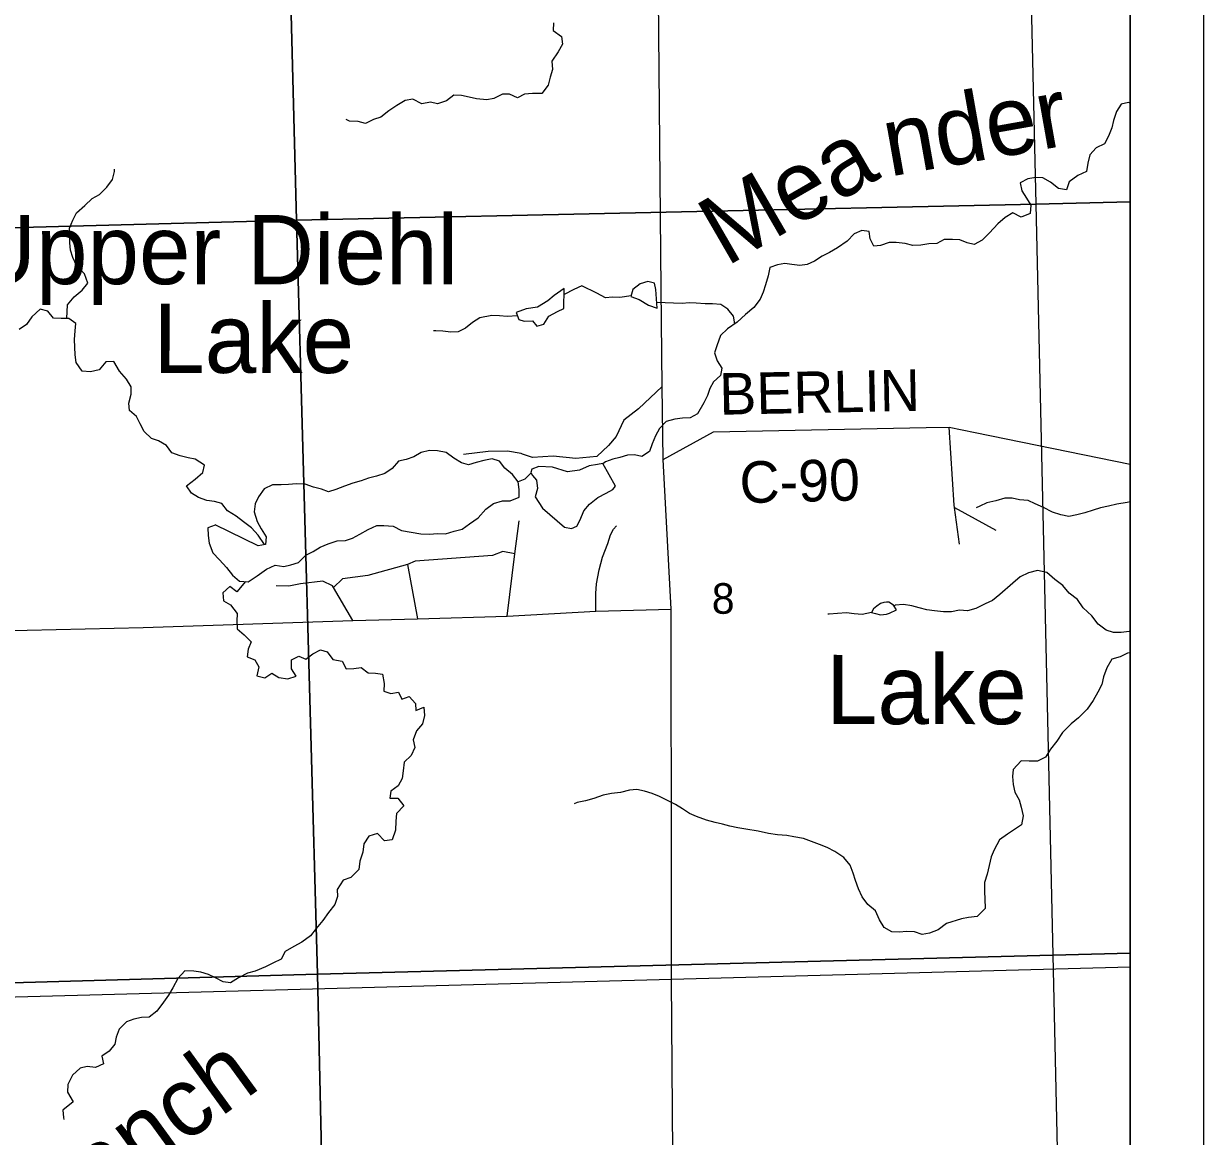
# Model space of a CAD drawing. Extents: x 0 to 34, y 0 to 22.
# Drawn here: x 8.73 to 10.344, y 14.503 to 16.025 of the extents above; entities that cross this region are included whole.
import ezdxf

# ---------------------------------------------------------------- set-up
doc = ezdxf.new("R2010")
doc.units = 0
for name, color, linetype in [('GM_X_Corporation', 7, 'Continuous'), ('GM_X_County_Road', 7, 'Continuous'), ('GM_X_County_Road_Text', 7, 'Continuous'), ('GM_X_Minor_Lake', 7, 'Continuous'), ('GM_X_Minor_Lake_Text', 7, 'Continuous'), ('GM_X_Minor_River', 7, 'Continuous'), ('GM_X_Minor_River_Text', 7, 'Continuous'), ('GM_X_Section_Text', 7, 'Continuous'), ('GM_X_State_Route', 7, 'Continuous'), ('GM_X_Township_Road', 7, 'Continuous'), ('SH_Data', 7, 'Continuous')]:
    doc.layers.add(name, color=color, linetype=linetype)

msp = doc.modelspace()

# ---------------------------------------------------------------- linework, layer by layer
at = {"layer": 'GM_X_Corporation'}
msp.add_lwpolyline([(7.068, 16.109), (7.0714, 16.0063), (7.0745, 15.896), (7.0787, 15.766), (7.0827, 15.6404), (7.0859, 15.5239), (7.0914, 15.3396), (7.0961, 15.1801), (7.0965, 15.1593), (7.1012, 14.6522), (7.1045, 14.5502), (7.1291, 13.6578), (8.1719, 13.6806), (8.628, 13.6922), (9.6344, 13.7177), (9.7208, 13.7198), (10.2438, 13.7323), (10.2438, 18.8341)], dxfattribs=at)
for points in [[(10.0909, 16.801), (10.1146, 15.7786), (9.1033, 15.7563), (9.0769, 16.778)], [(10.2438, 15.7815), (10.2438, 16.8039), (10.0909, 16.801), (10.1146, 15.7786)], [(9.0769, 16.778), (9.1033, 15.7563), (8.0922, 15.7295), (8.0702, 16.7576)], [(10.1146, 15.7786), (10.1377, 14.7507), (9.132, 14.7248), (9.1033, 15.7563)], [(10.2438, 14.7535), (10.2438, 15.7815), (10.1146, 15.7786), (10.1377, 14.7507)], [(9.1033, 15.7563), (9.132, 14.7248), (8.1182, 14.6962), (8.0922, 15.7295)], [(10.2438, 13.7318), (10.2438, 14.7535), (10.1377, 14.7507), (10.1605, 13.7298)], [(9.132, 14.7248), (10.1377, 14.7507), (10.1605, 13.7298), (9.7319, 13.7196), (9.155, 13.7064)], [(8.1182, 14.6962), (9.132, 14.7248), (9.155, 13.7064), (8.7319, 13.6926), (8.142, 13.6801)]]:
    msp.add_lwpolyline(points, close=True, dxfattribs=at)
at = {"layer": 'GM_X_County_Road'}
for p, q in [((9.6156, 15.2242), (9.6049, 15.4288)), ((10.2438, 14.7344), (9.6162, 14.7175))]:
    msp.add_line(p, q, dxfattribs=at)
for points in [[(9.6049, 15.4288), (9.6738, 15.4668), (9.9647, 15.4727), (9.9959, 15.4734), (10.0314, 15.4658), (10.2438, 15.4225)], [(7.0967, 15.1587), (8.735, 15.1956), (8.8937, 15.199), (9.1804, 15.2086), (9.2686, 15.2111), (9.3914, 15.2147), (9.5125, 15.2213), (9.6156, 15.2242)], [(9.6162, 14.7175), (8.5998, 14.6899), (7.1014, 14.6516)]]:
    msp.add_lwpolyline(points, dxfattribs=at)
at = {"layer": 'GM_X_Minor_Lake'}
for points in [[(9.5948, 15.6615), (9.5928, 15.6702), (9.5837, 15.6727), (9.5735, 15.6696), (9.5633, 15.6615), (9.5608, 15.6519), (9.5718, 15.6479), (9.5848, 15.6401), (9.5967, 15.636)], [(9.4692, 15.663), (9.4556, 15.6533), (9.447, 15.646), (9.4331, 15.6375), (9.4175, 15.635), (9.4039, 15.6303), (9.4075, 15.6204), (9.4147, 15.6182), (9.4261, 15.6188), (9.4319, 15.6116), (9.4417, 15.6144), (9.4484, 15.6251), (9.4605, 15.6313), (9.4691, 15.6356)], [(9.4691, 15.6356), (9.4692, 15.663)], [(9.5967, 15.636), (9.5948, 15.6615)], [(8.9919, 15.3396), (8.9919, 15.3392), (8.9821, 15.3357), (8.9826, 15.3251), (8.9839, 15.3145), (8.989, 15.3012), (8.9978, 15.2915), (9.0075, 15.281), (9.0155, 15.2709), (9.0251, 15.2626), (9.0373, 15.2617), (9.0496, 15.2698), (9.062, 15.2791), (9.074, 15.2845), (9.0858, 15.2828), (9.0956, 15.2848), (9.1058, 15.288), (9.1159, 15.298), (9.126, 15.3031), (9.1358, 15.3089), (9.1467, 15.3136), (9.1591, 15.3179), (9.1701, 15.3181), (9.1799, 15.3213), (9.19, 15.3267), (9.2013, 15.3333), (9.213, 15.3388), (9.2228, 15.3385), (9.2353, 15.3379), (9.2468, 15.332), (9.26, 15.3295), (9.2733, 15.3274), (9.2858, 15.3269), (9.2957, 15.3277), (9.307, 15.3275), (9.3187, 15.3311), (9.33, 15.3335), (9.3401, 15.3409), (9.3518, 15.349), (9.3622, 15.3609), (9.3727, 15.3686), (9.3851, 15.3726), (9.3954, 15.3723), (9.4078, 15.3774), (9.408, 15.3881), (9.4063, 15.3983), (9.3986, 15.4084), (9.3883, 15.417), (9.381, 15.4268), (9.3711, 15.4297), (9.3597, 15.4277), (9.3488, 15.4249), (9.3386, 15.4217), (9.3291, 15.4246), (9.3184, 15.4309), (9.3081, 15.4387), (9.2963, 15.4409), (9.2853, 15.4415), (9.274, 15.4387), (9.2639, 15.4328), (9.2533, 15.4289), (9.2428, 15.4269), (9.2342, 15.4165), (9.2241, 15.4099), (9.2128, 15.4063), (9.2018, 15.4035), (9.1917, 15.4), (9.1804, 15.3964), (9.1691, 15.3925), (9.157, 15.3881), (9.1472, 15.3846), (9.1373, 15.3886), (9.1263, 15.3911), (9.1153, 15.3952), (9.1031, 15.3958), (9.0925, 15.3949), (9.0823, 15.3943), (9.0706, 15.3942), (9.0589, 15.3887), (9.0515, 15.378), (9.0467, 15.3684), (9.0454, 15.3574), (9.0493, 15.3442), (9.0548, 15.334), (9.0618, 15.3231), (9.0608, 15.3128), (9.0509, 15.3108)], [(9.5222, 15.4234), (9.515, 15.4222), (9.5037, 15.4205), (9.4905, 15.4146), (9.4739, 15.4121), (9.4534, 15.4187), (9.4348, 15.4196), (9.425, 15.4156), (9.424, 15.4114), (9.4259, 15.4073), (9.4317, 15.4005), (9.433, 15.3892), (9.4297, 15.3781), (9.4398, 15.3623), (9.4697, 15.3365), (9.4795, 15.3344), (9.4867, 15.3379), (9.4915, 15.3463), (9.4962, 15.3589), (9.5041, 15.3677), (9.5153, 15.377), (9.5269, 15.3828), (9.536, 15.3879), (9.5397, 15.3925)], [(9.5397, 15.3925), (9.5222, 15.4234)], [(9.0509, 15.3108), (8.9919, 15.3396)], [(9.9198, 15.2298), (9.9137, 15.2339), (9.9103, 15.2339), (9.9065, 15.2334), (9.9023, 15.2319), (9.8971, 15.2284), (9.8926, 15.2245), (9.8896, 15.2195), (9.8953, 15.2181), (9.9022, 15.2163), (9.9101, 15.2172), (9.9146, 15.2187), (9.924, 15.2234)], [(9.924, 15.2234), (9.9198, 15.2298)]]:
    msp.add_lwpolyline(points, dxfattribs=at)
at = {"layer": 'GM_X_Minor_River'}
for points in [[(9.4547, 16.0264), (9.4544, 16.0161), (9.4656, 16.0079), (9.4672, 15.9973), (9.4613, 15.987), (9.4523, 15.974), (9.4536, 15.9626), (9.4503, 15.9523), (9.4474, 15.9412), (9.4388, 15.9297), (9.4263, 15.9299), (9.4153, 15.929), (9.4055, 15.924), (9.3948, 15.9288), (9.385, 15.9287), (9.3733, 15.9232), (9.3634, 15.9212), (9.3497, 15.9225), (9.3395, 15.9247), (9.3288, 15.9272), (9.3185, 15.9275), (9.3084, 15.9198), (9.2963, 15.9158), (9.2864, 15.918), (9.2747, 15.9156), (9.2624, 15.9219), (9.2518, 15.9202), (9.2405, 15.9136), (9.2296, 15.9059), (9.2187, 15.8974), (9.2085, 15.8942), (9.1976, 15.8888), (9.1877, 15.8913), (9.1759, 15.8919), (9.1713, 15.8942)], [(10.2438, 15.9167), (10.2414, 15.9174), (10.2315, 15.915), (10.2248, 15.9051), (10.2208, 15.8929), (10.2187, 15.883), (10.2139, 15.8715), (10.2083, 15.8608), (10.197, 15.8557), (10.1884, 15.8458), (10.1859, 15.8347), (10.1837, 15.8229), (10.172, 15.8178), (10.1604, 15.8089), (10.1564, 15.7979), (10.1457, 15.8), (10.1346, 15.8086), (10.1243, 15.8146), (10.1144, 15.8148), (10.1038, 15.8132), (10.0932, 15.8077), (10.0953, 15.7967), (10.1018, 15.7866), (10.1077, 15.7768), (10.107, 15.7657), (10.0946, 15.7606), (10.0831, 15.7666), (10.0726, 15.76), (10.0624, 15.7515), (10.0512, 15.7392), (10.0411, 15.7292), (10.0302, 15.7234), (10.0206, 15.7255), (10.0107, 15.7296), (10.0008, 15.7302), (9.9891, 15.7301)], [(8.7891, 15.622), (8.79, 15.6406), (8.7993, 15.6517), (8.8102, 15.6606), (8.8176, 15.6705), (8.8133, 15.683), (8.8025, 15.6943), (8.7974, 15.7052), (8.7939, 15.7154), (8.7934, 15.7256), (8.7932, 15.7355), (8.7927, 15.7454), (8.7971, 15.7564), (8.8023, 15.7664), (8.8135, 15.7764), (8.8236, 15.786), (8.8337, 15.7915), (8.8438, 15.8015), (8.8516, 15.8122), (8.8545, 15.8229), (8.8544, 15.8263)], [(9.9891, 15.7301), (9.9793, 15.7247), (9.9683, 15.7241), (9.9573, 15.7225), (9.9463, 15.722), (9.936, 15.7245), (9.9235, 15.7259), (9.914, 15.7258), (9.9023, 15.7218), (9.8928, 15.7209), (9.8881, 15.7311), (9.8868, 15.741), (9.8766, 15.7424), (9.866, 15.7377), (9.8563, 15.7277), (9.8431, 15.7188), (9.8325, 15.7122), (9.8224, 15.7072), (9.8118, 15.7002), (9.802, 15.6959), (9.7918, 15.6946), (9.7807, 15.696), (9.7712, 15.6974), (9.7614, 15.6954), (9.7508, 15.6915), (9.7483, 15.6801), (9.745, 15.6679), (9.7418, 15.6579), (9.7373, 15.6484), (9.7287, 15.6369), (9.7175, 15.6272), (9.7062, 15.6169), (9.693, 15.608), (9.6833, 15.5987), (9.6782, 15.5846), (9.6752, 15.5751), (9.6788, 15.5641), (9.685, 15.5539), (9.6832, 15.544), (9.6735, 15.5355), (9.6687, 15.526), (9.6654, 15.5164), (9.6606, 15.5065), (9.6516, 15.4916), (9.6418, 15.4861), (9.6312, 15.4856), (9.621, 15.4844), (9.6089, 15.4808), (9.5999, 15.4712), (9.5943, 15.4612), (9.5899, 15.4505), (9.5859, 15.4399), (9.5757, 15.4329), (9.5654, 15.4354), (9.5559, 15.4349), (9.5457, 15.4318), (9.5359, 15.4294), (9.5261, 15.4258), (9.5223, 15.4233)], [(9.5611, 15.653), (9.5456, 15.6506), (9.5357, 15.6512), (9.5259, 15.65), (9.514, 15.6567), (9.4934, 15.6667), (9.4828, 15.6616), (9.4692, 15.655)], [(9.703, 15.6147), (9.7012, 15.6251), (9.6935, 15.6349), (9.6839, 15.6413), (9.6721, 15.6419), (9.6622, 15.6422), (9.6501, 15.6428), (9.6402, 15.6434), (9.6307, 15.6425), (9.619, 15.6428), (9.6076, 15.6434), (9.5961, 15.6437)], [(9.0597, 15.3126), (9.0507, 15.3256), (9.0415, 15.3353), (9.0308, 15.3436), (9.0209, 15.3514), (9.009, 15.3588), (9.0009, 15.3686), (8.991, 15.3715), (8.9804, 15.3729), (8.9694, 15.3769), (8.9598, 15.3828), (8.9529, 15.393), (8.9645, 15.4019), (8.975, 15.4111), (8.9775, 15.4214), (8.9645, 15.4296), (8.955, 15.4314), (8.944, 15.4339), (8.9329, 15.4383), (8.9256, 15.448), (8.9145, 15.4547), (8.9047, 15.4576), (8.8951, 15.4674), (8.8896, 15.4779), (8.8842, 15.4877), (8.8746, 15.4959), (8.8741, 15.5062), (8.8769, 15.5184), (8.8772, 15.5286), (8.8706, 15.5388), (8.861, 15.5497), (8.8532, 15.5632), (8.8426, 15.5627), (8.8333, 15.5519), (8.8216, 15.5488), (8.8102, 15.5501), (8.8017, 15.5618), (8.8005, 15.572), (8.7994, 15.5932), (8.8004, 15.605), (8.8014, 15.6149), (8.7918, 15.622), (8.7812, 15.6218), (8.771, 15.6225), (8.7633, 15.6322), (8.7526, 15.6348), (8.741, 15.6243), (8.734, 15.6136), (8.7239, 15.6067)], [(9.4055, 15.6258), (9.3915, 15.6248), (9.3808, 15.6258), (9.3706, 15.6261), (9.3539, 15.6228), (9.3441, 15.6166), (9.3344, 15.6089), (9.3242, 15.6035), (9.3143, 15.6033), (9.3033, 15.6047), (9.2938, 15.605), (9.2908, 15.605)], [(9.4243, 15.4108), (9.4155, 15.4021), (9.4063, 15.3983)], [(10.2438, 15.371), (10.2396, 15.37), (10.2256, 15.3679), (10.2139, 15.3651), (10.203, 15.3627), (10.1932, 15.3595), (10.1815, 15.3559), (10.1709, 15.3535), (10.1596, 15.3511), (10.1486, 15.3532), (10.1372, 15.3568), (10.125, 15.3631), (10.1139, 15.3683), (10.104, 15.3731), (10.0923, 15.3737), (10.082, 15.3762), (10.0722, 15.3761), (10.0601, 15.3725), (10.0477, 15.3697), (10.0379, 15.365), (10.033, 15.363)], [(10.2438, 15.1938), (10.2421, 15.1935), (10.2311, 15.1922), (10.2209, 15.1921), (10.211, 15.1954), (10.1999, 15.2036), (10.1911, 15.2152), (10.1795, 15.2261), (10.1718, 15.2374), (10.16, 15.2463), (10.1515, 15.2568), (10.1404, 15.265), (10.1297, 15.2744), (10.1171, 15.2772), (10.1047, 15.274), (10.093, 15.2686), (10.0833, 15.2597), (10.0653, 15.2443), (10.0552, 15.2362), (10.0451, 15.2315), (10.0323, 15.2252), (10.021, 15.2217), (10.01, 15.223), (9.9994, 15.2206), (9.9881, 15.2205), (9.9759, 15.2218), (9.9657, 15.2232), (9.955, 15.2261), (9.9448, 15.2286), (9.9334, 15.2308), (9.9224, 15.2295), (9.9207, 15.2284)], [(9.0333, 15.262), (9.0215, 15.2478), (9.012, 15.2552), (9.0023, 15.2464), (9.0032, 15.2354), (9.0131, 15.2302), (9.022, 15.2182), (9.0217, 15.2076), (9.0219, 15.1973), (9.0318, 15.1891), (9.0414, 15.1794), (9.037, 15.1694), (9.0357, 15.1588), (9.0463, 15.1551), (9.0518, 15.1453), (9.0489, 15.1331), (9.0599, 15.1303), (9.0697, 15.1368), (9.0792, 15.1309), (9.0914, 15.1288), (9.1027, 15.1323), (9.0965, 15.1425), (9.0963, 15.1547), (9.1064, 15.1601), (9.116, 15.1557), (9.1257, 15.163), (9.1359, 15.1685), (9.1454, 15.1656), (9.1531, 15.1554), (9.1656, 15.1529), (9.171, 15.1424), (9.1816, 15.1429), (9.1915, 15.1442), (9.2014, 15.1371), (9.2113, 15.1368), (9.2211, 15.1354), (9.2232, 15.1226), (9.2226, 15.1119), (9.2321, 15.1086), (9.243, 15.1107), (9.2473, 15.1009), (9.2575, 15.1048), (9.266, 15.0951), (9.2665, 15.0856), (9.2774, 15.0899), (9.2783, 15.0789), (9.2755, 15.0671), (9.2676, 15.0575), (9.2629, 15.0453), (9.2653, 15.0351), (9.2602, 15.024), (9.2504, 15.0148), (9.2491, 15.003), (9.2477, 14.9923), (9.2422, 14.9824), (9.2325, 14.975), (9.2311, 14.9655), (9.242, 14.9657), (9.2501, 14.9552), (9.2401, 14.9444), (9.2391, 14.9341), (9.2389, 14.9216), (9.2341, 14.9086), (9.2236, 14.9074), (9.214, 14.9171), (9.2023, 14.9135), (9.1952, 14.9032), (9.1939, 14.8918), (9.1899, 14.8796), (9.1885, 14.8682), (9.1777, 14.857), (9.1671, 14.8535), (9.159, 14.8405), (9.1595, 14.831), (9.1555, 14.8199), (9.147, 14.8092), (9.1392, 14.7981), (9.1302, 14.7873), (9.1224, 14.777), (9.1104, 14.7685), (9.0995, 14.7626), (9.0879, 14.7556), (9.0824, 14.7453), (9.0707, 14.7398), (9.0609, 14.7348), (9.0466, 14.7289), (9.0361, 14.7261), (9.024, 14.7199), (9.0131, 14.7129), (9.0029, 14.7143), (8.9926, 14.7198), (8.9827, 14.7242), (8.9724, 14.7275), (8.9626, 14.7289), (8.9505, 14.7291), (8.9411, 14.7187), (8.9341, 14.7061), (8.9282, 14.6962), (8.9215, 14.6866), (8.9122, 14.6743), (8.9018, 14.6658)], [(9.8896, 15.2195), (9.8772, 15.2171), (9.8662, 15.2177), (9.8556, 15.2191), (9.8435, 15.2182), (9.8321, 15.2173), (9.8299, 15.2172)], [(10.2438, 15.1645), (10.2402, 15.1639), (10.2301, 15.1588), (10.2184, 15.1556), (10.2117, 15.1441), (10.207, 15.1316), (10.2049, 15.1209), (10.1993, 15.1106), (10.1931, 15.0991), (10.1849, 15.0872), (10.1729, 15.0757), (10.1628, 15.0672), (10.1509, 15.0553), (10.1431, 15.0434), (10.1346, 15.0327), (10.1279, 15.0216), (10.117, 15.0161), (10.1053, 15.0163), (10.0946, 15.0166), (10.0838, 15.0047), (10.0825, 14.9951), (10.0834, 14.9845), (10.0858, 14.9736), (10.092, 14.9634), (10.0944, 14.9532), (10.0972, 14.9414), (10.0951, 14.9293), (10.076, 14.9161), (10.0651, 14.9084), (10.0577, 14.895), (10.0533, 14.8851), (10.0508, 14.8733), (10.048, 14.8618), (10.0444, 14.85), (10.0442, 14.8375), (10.045, 14.828), (10.0452, 14.8147), (10.0344, 14.8036), (10.0227, 14.8023), (10.0129, 14.8003), (9.9925, 14.7939), (9.9809, 14.7854), (9.9692, 14.7807), (9.959, 14.779), (9.9484, 14.7827), (9.9378, 14.7833), (9.9279, 14.7824), (9.9177, 14.7827), (9.907, 14.7886), (9.9008, 14.7991), (9.8954, 14.8116), (9.885, 14.8202), (9.8769, 14.8307), (9.8719, 14.8413), (9.8679, 14.853), (9.8647, 14.8628), (9.8604, 14.8738), (9.8519, 14.8846), (9.8397, 14.8928), (9.829, 14.898), (9.8188, 14.902), (9.8077, 14.9061), (9.7967, 14.9105), (9.7834, 14.9126), (9.7739, 14.9143), (9.7614, 14.9153), (9.7489, 14.9174), (9.7348, 14.9203), (9.7181, 14.9231), (9.7068, 14.9248), (9.6961, 14.9274), (9.6862, 14.9299), (9.676, 14.9324), (9.6642, 14.9353), (9.6505, 14.9404), (9.641, 14.9445), (9.6311, 14.9512), (9.6215, 14.9567), (9.6108, 14.9626), (9.5998, 14.9678), (9.5899, 14.9722), (9.5792, 14.9751), (9.569, 14.9773), (9.5588, 14.9764), (9.5463, 14.9732), (9.5342, 14.9722), (9.5229, 14.9698), (9.5101, 14.9651), (9.4988, 14.9619), (9.4871, 14.9595), (9.4833, 14.9579)], [(8.9018, 14.6658), (8.8912, 14.6653), (8.8806, 14.6633), (8.8708, 14.6594), (8.8607, 14.6497), (8.8567, 14.6387), (8.8549, 14.6288), (8.8471, 14.6192), (8.837, 14.6126), (8.8394, 14.602), (8.8285, 14.5969), (8.8171, 14.5983), (8.8073, 14.5963), (8.7969, 14.5866), (8.7906, 14.5736), (8.79, 14.5634), (8.7977, 14.5502), (8.7835, 14.5386), (8.7844, 14.5288), (8.7848, 14.5261)]]:
    msp.add_lwpolyline(points, dxfattribs=at)
at = {"layer": 'GM_X_State_Route'}
for p, q in [((9.6021, 15.6624), (9.5969, 16.2262)), ((9.6156, 15.2242), (9.6049, 15.4288)), ((9.6161, 14.8467), (9.6156, 15.2242))]:
    msp.add_line(p, q, dxfattribs=at)
for points in [[(9.6049, 15.4288), (9.6033, 15.5291), (9.6021, 15.6624)], [(9.618, 14.4794), (9.6162, 14.7175), (9.6161, 14.8467)]]:
    msp.add_lwpolyline(points, dxfattribs=at)
at = {"layer": 'GM_X_Township_Road'}
for p, q in [((10.003, 15.3664), (9.9959, 15.4734)), ((10.0033, 15.3632), (10.0599, 15.3321)), ((9.2551, 15.2853), (9.2686, 15.2111))]:
    msp.add_line(p, q, dxfattribs=at)
for points in [[(9.6033, 15.5291), (9.571, 15.4985), (9.551, 15.4827), (9.5406, 15.4607), (9.53, 15.4482), (9.5141, 15.4333), (9.4853, 15.4305), (9.4545, 15.4334), (9.4261, 15.4318), (9.4123, 15.4364)], [(9.4123, 15.4364), (9.4104, 15.437), (9.3917, 15.4406), (9.3655, 15.4398), (9.3315, 15.4358)], [(10.0103, 15.313), (10.0033, 15.3632), (10.003, 15.3664)], [(9.3914, 15.2147), (9.4021, 15.2997), (9.4078, 15.3449)], [(9.5125, 15.2213), (9.5125, 15.2458), (9.5138, 15.2591), (9.5173, 15.2781), (9.522, 15.2953), (9.5292, 15.3141), (9.5329, 15.3257), (9.5371, 15.3339), (9.5408, 15.3384)], [(9.4021, 15.2997), (9.3854, 15.3031), (9.3712, 15.2978), (9.2655, 15.29), (9.2551, 15.2853), (9.2008, 15.2702), (9.1664, 15.2658), (9.154, 15.2539)], [(9.1804, 15.2086), (9.154, 15.2539), (9.1526, 15.2562), (9.1391, 15.2627), (9.1085, 15.2591), (9.0927, 15.2556), (9.0756, 15.2562)]]:
    msp.add_lwpolyline(points, dxfattribs=at)
at = {"layer": 'SH_Data'}
for p, q in [((10.3438, 20.0239), (10.3438, 13.0239)), ((10.2438, 19.9239), (10.2438, 13.1239))]:
    msp.add_line(p, q, dxfattribs=at)

# ---------------------------------------------------------------- texts
at = {"layer": 'GM_X_County_Road_Text'}
for s, rotation, p in [('BERLIN', 1.1421, (9.6821, 15.4902)), ('C-90', 1.3713, (9.7099, 15.3692))]:
    msp.add_text(s, height=0.05682, rotation=rotation, dxfattribs=at).set_placement(p)
at = {"layer": 'GM_X_Minor_Lake_Text'}
for s, height, rotation, p in [('Upper Diehl', 0.094732, 359.9569, (8.6554, 15.6691)), ('Lake', 0.09473, 359.9568, (8.9073, 15.5476))]:
    msp.add_text(s, height=height, rotation=rotation, dxfattribs=at).set_placement(p)
at = {"layer": 'GM_X_Minor_River_Text'}
for s, rotation, p in [('nder', 10.0327, (9.9142, 15.8159)), ('Mea', 30.0339, (9.6911, 15.6923)), ('Lake', 359.9561, (9.8275, 15.067)), ('Branch', 35.9921, (8.7316, 14.3341))]:
    msp.add_text(s, height=0.09473, rotation=rotation, dxfattribs=at).set_placement(p)
at = {"layer": 'GM_X_Section_Text'}
msp.add_text('8', height=0.0419, rotation=0, dxfattribs=at).set_placement((9.6713, 15.2179))

doc.saveas('drawing.dxf')
